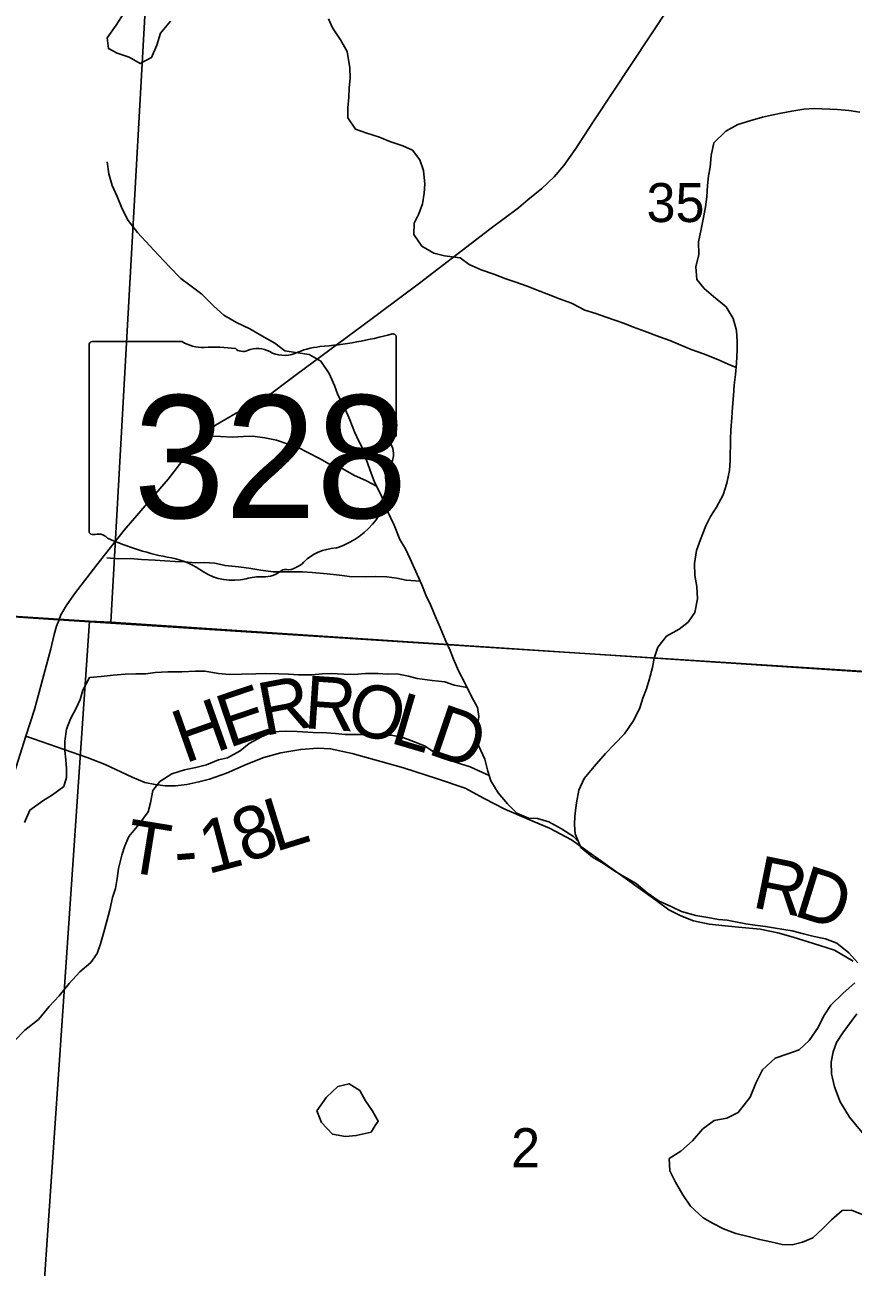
# Model space of a CAD drawing. Extents: x 0 to 34, y 0 to 22.
# Drawn here: x 3.309 to 4.198, y 18.42 to 19.753 of the extents above; entities that cross this region are included whole.
import ezdxf

# ---------------------------------------------------------------- set-up
doc = ezdxf.new("R2010")
doc.units = 0
for name, color, linetype in [('GM_X_Major_River', 7, 'Continuous'), ('GM_X_Minor_Lake', 7, 'Continuous'), ('GM_X_Minor_River', 7, 'Continuous'), ('GM_X_Section', 7, 'Continuous'), ('GM_X_Section_Text', 7, 'Continuous'), ('GM_X_State_Location', 7, 'Continuous'), ('GM_X_State_Route', 7, 'Continuous'), ('GM_X_State_Shield', 7, 'Continuous'), ('GM_X_Township_Road', 7, 'Continuous'), ('GM_X_Township_Road_Text', 7, 'Continuous'), ('SC_Scratch1', 7, 'Continuous')]:
    doc.layers.add(name, color=color, linetype=linetype)

msp = doc.modelspace()

# ---------------------------------------------------------------- linework, layer by layer
at = {"layer": 'GM_X_Major_River'}
for points in [[(3.9032, 18.9318), (3.909, 18.9443), (3.9197, 18.9571), (3.9319, 18.9711), (3.9415, 18.9812), (3.9525, 18.9922), (3.9625, 19.0069), (3.969, 19.0201), (3.9721, 19.0307), (3.976, 19.0405), (3.9787, 19.0504), (3.9826, 19.0636), (3.9842, 19.0735), (3.9881, 19.0852), (3.9976, 19.0973), (4.011, 19.1048), (4.0209, 19.1123), (4.0278, 19.1225), (4.0309, 19.1373), (4.0302, 19.1505), (4.028, 19.1623), (4.0274, 19.1752), (4.0297, 19.1892), (4.034, 19.201), (4.0398, 19.2157), (4.0448, 19.2255), (4.0513, 19.2357), (4.0582, 19.249), (4.0621, 19.2615), (4.0652, 19.2751), (4.066, 19.2853), (4.0662, 19.3088), (4.0666, 19.3183), (4.0675, 19.332), (4.0683, 19.343), (4.0695, 19.3555), (4.07, 19.3665), (4.0716, 19.3782), (4.0728, 19.3903), (4.0732, 19.404), (4.0733, 19.4135), (4.0726, 19.4252), (4.0689, 19.4382), (4.0614, 19.4507), (4.0478, 19.4618), (4.038, 19.4703), (4.0301, 19.4802), (4.0291, 19.4938), (4.0322, 19.5067), (4.0319, 19.5204), (4.0347, 19.534), (4.0374, 19.5484), (4.0394, 19.5579), (4.0406, 19.5689), (4.0414, 19.581), (4.0426, 19.5912), (4.0442, 19.6007), (4.0454, 19.6132), (4.0482, 19.6269), (4.0611, 19.6393), (4.0741, 19.6464), (4.087, 19.6505), (4.1007, 19.6542), (4.1102, 19.6564), (4.1205, 19.6586), (4.1322, 19.6608), (4.1451, 19.6629), (4.1561, 19.6636), (4.1812, 19.6627), (4.1933, 19.6614), (4.205, 19.6598)], [(4.2028, 18.7464), (4.1934, 18.7571), (4.1805, 18.7674), (4.1681, 18.7721), (4.1559, 18.7748), (4.1446, 18.7775), (4.1325, 18.7807), (4.1146, 18.7835), (4.1037, 18.7854), (4.0923, 18.787), (4.0828, 18.7882), (4.0734, 18.7902), (4.0627, 18.7922), (4.0533, 18.793), (4.0419, 18.795), (4.029, 18.7974), (4.0135, 18.8017), (4.0033, 18.8067), (3.9897, 18.8125), (3.9768, 18.8216), (3.9648, 18.8316), (3.9542, 18.8378), (3.9421, 18.8447), (3.93, 18.8531), (3.9179, 18.86), (3.9055, 18.8704), (3.8995, 18.8848), (3.8988, 18.8947), (3.8992, 18.9042), (3.9009, 18.9182), (3.9032, 18.9318)], [(4.2093, 18.4755), (4.1961, 18.4809), (4.1862, 18.4806), (4.1748, 18.4704), (4.1649, 18.461), (4.1546, 18.4512), (4.1435, 18.4464), (4.1325, 18.4438), (4.1215, 18.4442), (4.1094, 18.447), (4.0976, 18.4494), (4.0852, 18.4525), (4.0719, 18.456), (4.0587, 18.461), (4.0469, 18.4668), (4.0367, 18.4726), (4.0232, 18.4852), (4.0149, 18.4974), (4.007, 18.5111), (4.001, 18.5233), (4.0004, 18.5362), (4.0129, 18.5441), (4.0255, 18.5554), (4.0366, 18.5682), (4.0488, 18.5772), (4.0621, 18.5797), (4.0743, 18.5857), (4.0873, 18.6023), (4.0934, 18.6174), (4.1007, 18.6314), (4.1141, 18.6439), (4.1278, 18.6487), (4.14, 18.6531), (4.1506, 18.6629), (4.1602, 18.6769), (4.1664, 18.6894), (4.174, 18.7011), (4.187, 18.7139), (4.1996, 18.7248)]]:
    msp.add_lwpolyline(points, dxfattribs=at)
at = {"layer": 'GM_X_Minor_Lake'}
for points in [[(3.6848, 18.5718), (3.6879, 18.5765), (3.6814, 18.5879), (3.6742, 18.5981), (3.6681, 18.6095), (3.6567, 18.6166), (3.6446, 18.6136), (3.6325, 18.6022), (3.622, 18.5874)], [(3.622, 18.5874), (3.6269, 18.5749), (3.6387, 18.5624), (3.6527, 18.5601), (3.6644, 18.5609), (3.6803, 18.5647), (3.6848, 18.5718)]]:
    msp.add_lwpolyline(points, dxfattribs=at)
at = {"layer": 'GM_X_Minor_River'}
for points in [[(3.4649, 19.7573), (3.4543, 19.7444), (3.4502, 19.7315), (3.4446, 19.7182), (3.4325, 19.7118), (3.4207, 19.7186), (3.4078, 19.7231), (3.3983, 19.728), (3.3968, 19.7393), (3.4066, 19.753), (3.4149, 19.7659)], [(4.0723, 19.3857), (4.0638, 19.3892), (4.0509, 19.3948), (4.0372, 19.4001), (4.024, 19.405), (4.0103, 19.4106), (4.0009, 19.4144), (3.9899, 19.4186), (3.9739, 19.4246), (3.9622, 19.4287), (3.9523, 19.4329), (3.9421, 19.4363), (3.9326, 19.4396), (3.9216, 19.4434), (3.9099, 19.4472), (3.8955, 19.4547), (3.8826, 19.4592), (3.8709, 19.4641), (3.8614, 19.4675), (3.8477, 19.4728), (3.8345, 19.4777), (3.825, 19.4807), (3.8121, 19.4856), (3.7985, 19.4905), (3.7856, 19.4962), (3.7761, 19.5033), (3.7591, 19.5056), (3.7477, 19.5082), (3.7348, 19.5157), (3.726, 19.5282), (3.7264, 19.5404), (3.7317, 19.5506), (3.7354, 19.5612), (3.7373, 19.5726), (3.738, 19.5825), (3.7364, 19.5969), (3.7326, 19.6086), (3.7246, 19.6188), (3.7144, 19.6234), (3.7004, 19.6283), (3.6894, 19.6328), (3.6757, 19.6373), (3.6636, 19.6414), (3.6552, 19.6535), (3.6552, 19.6642), (3.6563, 19.6759), (3.6566, 19.6858), (3.6577, 19.696), (3.6573, 19.7074), (3.6546, 19.7248), (3.6474, 19.7373), (3.639, 19.7502), (3.6345, 19.76)], [(3.903, 18.8764), (3.8977, 18.8819), (3.8848, 18.8902), (3.8712, 18.8977), (3.859, 18.9015), (3.8492, 18.9018), (3.8367, 18.9071), (3.8268, 18.917), (3.8169, 18.9291), (3.8089, 18.9419), (3.8055, 18.9522), (3.8024, 18.965), (3.796, 18.9791), (3.7933, 18.9919), (3.7944, 19.0014), (3.7959, 19.0109), (3.7947, 19.0204), (3.7882, 19.0325), (3.781, 19.0469), (3.7741, 19.0598), (3.7688, 19.0723), (3.7653, 19.0817), (3.7604, 19.0916), (3.7543, 19.1063), (3.7493, 19.1177), (3.7444, 19.1302), (3.7394, 19.1404), (3.7348, 19.1522), (3.7283, 19.1666), (3.7222, 19.1802), (3.7173, 19.1908), (3.7112, 19.201), (3.7051, 19.2162), (3.6975, 19.2321), (3.691, 19.2484), (3.6838, 19.2624), (3.6803, 19.2722), (3.6753, 19.2859), (3.6727, 19.2953), (3.667, 19.3063), (3.6624, 19.3165), (3.6574, 19.3294), (3.6517, 19.3427), (3.6445, 19.3563), (3.641, 19.3661), (3.6353, 19.379), (3.6262, 19.3923), (3.6137, 19.3994), (3.6015, 19.4013), (3.5875, 19.4035), (3.5769, 19.4115), (3.5629, 19.4194), (3.55, 19.427), (3.5359, 19.4337), (3.5223, 19.4417), (3.5113, 19.4515), (3.4984, 19.4644), (3.4855, 19.4738), (3.476, 19.481), (3.4642, 19.4931), (3.4521, 19.5063), (3.4426, 19.5162), (3.4296, 19.5305), (3.4194, 19.5434), (3.4129, 19.5559), (3.4076, 19.5692), (3.4022, 19.5809), (3.3988, 19.5934), (3.3968, 19.6063)], [(3.686, 19.258), (3.6754, 19.2639), (3.6618, 19.2699), (3.65, 19.2767), (3.6383, 19.2805), (3.625, 19.288), (3.6125, 19.2944), (3.6011, 19.3001), (3.5913, 19.3031), (3.5787, 19.3076), (3.5662, 19.3099), (3.5534, 19.3117), (3.5432, 19.3113), (3.531, 19.3109), (3.5185, 19.3116), (3.5068, 19.312)], [(3.733, 19.1563), (3.7178, 19.1571), (3.7079, 19.1593), (3.6973, 19.1608), (3.6848, 19.1611), (3.6742, 19.1607), (3.6572, 19.1611), (3.6462, 19.1626), (3.633, 19.1641), (3.6171, 19.1655), (3.6068, 19.1663), (3.575, 19.1662), (3.5618, 19.168), (3.5489, 19.1703), (3.5379, 19.1714), (3.5235, 19.1729), (3.5125, 19.1755), (3.5012, 19.1762), (3.4913, 19.1758), (3.4804, 19.1769), (3.4698, 19.1773), (3.4588, 19.178), (3.4486, 19.1788), (3.4338, 19.1795), (3.4217, 19.1806), (3.4088, 19.1802), (3.3967, 19.1813)], [(3.7834, 19.042), (3.7696, 19.0446), (3.7594, 19.048), (3.7458, 19.0495), (3.7299, 19.0517), (3.7204, 19.0543), (3.7079, 19.0566), (3.698, 19.0562), (3.6878, 19.0569), (3.6742, 19.0569), (3.6617, 19.0561), (3.6511, 19.0564), (3.6375, 19.0572), (3.6276, 19.0567), (3.6167, 19.0556), (3.6023, 19.0555), (3.5917, 19.0563), (3.5811, 19.0566), (3.5671, 19.057), (3.5565, 19.0566), (3.5413, 19.0562), (3.5281, 19.0561), (3.5163, 19.0572), (3.5019, 19.0595), (3.4917, 19.0594), (3.477, 19.0587), (3.4622, 19.059), (3.4486, 19.0582), (3.4384, 19.0567), (3.4278, 19.0566), (3.4164, 19.0562), (3.4035, 19.0554), (3.3903, 19.0539), (3.3778, 19.0527), (3.3707, 19.0391), (3.368, 19.0292), (3.3635, 19.0197), (3.3575, 19.0083), (3.3534, 18.9973), (3.3515, 18.9844), (3.3516, 18.9742), (3.3524, 18.9643), (3.3531, 18.9549), (3.3532, 18.9454), (3.3502, 18.9359), (3.3381, 18.9268), (3.3279, 18.9203), (3.3139, 18.9104), (3.3083, 18.8971)], [(3.8071, 18.9474), (3.796, 18.9525), (3.7866, 18.9567), (3.7763, 18.9601), (3.7665, 18.9634), (3.7517, 18.9702), (3.7384, 18.9789), (3.7286, 18.9831), (3.7142, 18.9883), (3.702, 18.991), (3.6914, 18.9909), (3.6793, 18.9917), (3.6524, 18.9916), (3.6422, 18.9927), (3.6324, 18.9934), (3.618, 18.9938), (3.601, 18.9949), (3.5881, 18.9952), (3.5748, 18.9944), (3.5627, 18.9891), (3.5495, 18.9819), (3.5397, 18.9739), (3.5261, 18.9666), (3.5163, 18.9643), (3.5034, 18.959), (3.4921, 18.9563), (3.48, 18.9536), (3.4663, 18.9494), (3.4535, 18.9411), (3.446, 18.9316), (3.4433, 18.9183), (3.4411, 18.9084), (3.4309, 18.8951), (3.42, 18.8822), (3.4159, 18.872), (3.4125, 18.8621), (3.4091, 18.8477), (3.4076, 18.8371), (3.4058, 18.8264), (3.4028, 18.8166), (3.3998, 18.8033), (3.3968, 18.7927), (3.3934, 18.7794), (3.3897, 18.7669), (3.386, 18.7563), (3.3792, 18.7468), (3.3675, 18.7369), (3.3562, 18.7243), (3.3452, 18.711), (3.3347, 18.6996), (3.323, 18.6856), (3.3086, 18.6742), (3.2973, 18.6628)]]:
    msp.add_lwpolyline(points, dxfattribs=at)
at = {"layer": 'GM_X_Section'}
for points in [[(3.4572, 20.1141), (3.4007, 19.112), (3.378, 19.1131), (2.3838, 19.1776), (2.446, 20.1823)], [(4.4687, 20.0485), (4.4009, 19.0464), (4.3808, 19.0475), (3.4007, 19.112), (3.4572, 20.1141)], [(2.3543, 19.1806), (2.3838, 19.1776), (3.378, 19.1131), (3.3075, 18.0826), (2.2906, 18.1558)], [(3.378, 19.1131), (3.4007, 19.112), (4.3808, 19.0475), (4.3187, 18.0057), (3.3075, 18.0826)]]:
    msp.add_lwpolyline(points, close=True, dxfattribs=at)
at = {"layer": 'GM_X_State_Route'}
for points in [[(3.8486, 19.5654), (3.8636, 19.5777), (3.8768, 19.5901), (3.8872, 19.6025), (3.8994, 19.6195), (3.9187, 19.6494), (4.0213, 19.8045)], [(3.6886, 19.4434), (3.7324, 19.476), (3.8076, 19.5342), (3.8384, 19.557), (3.8486, 19.5654)], [(3.3095, 18.9897), (3.3188, 19.0184), (3.3365, 19.0837), (3.3399, 19.0989), (3.3424, 19.1077), (3.345, 19.1141), (3.3473, 19.1199), (3.353, 19.1297), (3.3618, 19.1426), (3.3859, 19.1737), (3.4153, 19.211), (3.4623, 19.2657), (3.4869, 19.2972), (3.4966, 19.3092), (3.5131, 19.3237), (3.5354, 19.3366), (3.5641, 19.351), (3.6003, 19.378), (3.6813, 19.438), (3.6886, 19.4434)], [(3.2872, 18.9182), (3.3095, 18.9897)]]:
    msp.add_lwpolyline(points, dxfattribs=at)
at = {"layer": 'GM_X_State_Shield'}
for p, q in [((3.3776, 19.4099), (3.3776, 19.2097)), ((3.4774, 19.4133), (3.3809, 19.4133)), ((3.7072, 19.3136), (3.7072, 19.4183)), ((3.7072, 19.3136), (3.7072, 19.3136))]:
    msp.add_line(p, q, dxfattribs=at)
for centre, major_axis, start_param, end_param in [((3.5898, 19.6861), (0.3495, 0), 4.814394, 5.042369), ((3.7036, 19.4187), (0.00367, 0), 6.141152, 7.989035), ((3.3814, 19.4103), (0.00382, 0), 1.712693, 3.28349), ((3.5004, 19.4365), (0.037, 0), 4.042523, 4.731795), ((3.5127, 19.301), (0.133, 0), 1.404758, 1.657858), ((3.5428, 19.4113), (0.0107, 0), 3.836095, 5.185415), ((3.5585, 19.3882), (0.0222, 0), 0.950623, 2.079405), ((3.6344, 19.3522), (0.0703, 0), 1.699011, 2.107814), ((3.5872, 19.4199), (0.0267, 0), 4.081561, 5.145723), ((3.7033, 19.3132), (0.00393, 0), 5.05454, 6.418171), ((3.7064, 19.3059), (0.00568, 0), 1.883978, 3.671073), ((3.6702, 19.2927), (0.0341, 0), 5.934695, 6.695948), ((3.7204, 19.2698), (0.0248, 0), 2.387724, 3.262537), ((3.6094, 19.2564), (0.0874, 0), 5.101752, 6.440018), ((3.3814, 19.2093), (0.00385, 0), 3.00124, 4.508301), ((3.382, 19.2298), (0.0294, 0), 4.665946, 4.897461), ((3.388, 19.1982), (0.0106, 0), 0.519207, 1.627899), ((3.5219, 19.378), (0.2524, 0), 4.195997, 4.488961), ((3.4466, 19.1198), (0.079, 0), 0.823519, 1.323587), ((3.6463, 19.1536), (0.0479, 0), 1.647645, 2.488434), ((3.532, 19.1972), (0.0501, 0), 4.026481, 4.996735), ((3.5646, 19.1822), (0.0267, 0), 4.691044, 5.507374), ((3.5888, 19.1628), (0.00752, 0), 1.147584, 2.315152), ((3.5856, 19.1903), (0.0282, 0), 4.937069, 5.64225), ((3.561, 19.128), (0.0412, 0), 1.495662, 1.94098)]:
    msp.add_ellipse(centre, major_axis=major_axis, ratio=0.8, start_param=start_param, end_param=end_param, dxfattribs=at)
at = {"layer": 'GM_X_Township_Road'}
for points in [[(3.3095, 18.9897), (3.3756, 18.9667), (3.3949, 18.9593), (3.4237, 18.9459), (3.4372, 18.9402), (3.4485, 18.9377), (3.4593, 18.9365), (3.4703, 18.9365), (3.4823, 18.9377), (3.4955, 18.9406), (3.5067, 18.9436), (3.5249, 18.9499), (3.5463, 18.9593), (3.5651, 18.9669), (3.5833, 18.9719), (3.6047, 18.9756), (3.6231, 18.9768), (3.6367, 18.9763), (3.6599, 18.971), (3.7151, 18.9556), (3.7517, 18.9439), (3.7814, 18.9338), (3.8016, 18.9227), (3.8239, 18.9114), (3.8495, 18.9004), (3.872, 18.891), (3.8955, 18.8785), (3.9341, 18.8509), (3.9859, 18.8137), (4.0001, 18.8035), (4.013, 18.7969), (4.0266, 18.7914), (4.0434, 18.7881), (4.0604, 18.7861), (4.0747, 18.7847), (4.0981, 18.7824), (4.117, 18.7787), (4.1336, 18.7741), (4.1554, 18.7672), (4.178, 18.7601), (4.198, 18.7481)], [(4.2017, 18.6915), (4.1869, 18.6713), (4.18, 18.6609), (4.1763, 18.6508), (4.1743, 18.6398), (4.1747, 18.6273), (4.178, 18.6133), (4.1839, 18.5972), (4.1938, 18.5809), (4.2143, 18.556)]]:
    msp.add_lwpolyline(points, dxfattribs=at)
at = {"layer": 'SC_Scratch1'}
for points in [[(5.53, 20.9), (2.1, 20.9), (2.1, 19.1982), (2.3572, 19.1804), (3.3448, 19.1146), (4.3628, 19.0495), (4.7394, 19.0241), (4.7997, 19.0196), (5.182, 18.9932), (5.4007, 18.9779), (5.4089, 19.0989), (5.4469, 19.6641), (5.4955, 20.3864)], [(2.1, 19.1982), (2.1, 14.1), (5.0535, 14.1), (5.0814, 14.5016), (5.1049, 14.8414), (5.1794, 15.9156), (5.2761, 17.2534), (5.2869, 17.4026), (5.3506, 18.2846), (5.3662, 18.4999), (5.4007, 18.9779), (5.182, 18.9932), (4.7997, 19.0196), (4.7394, 19.0241), (4.3628, 19.0495), (3.3448, 19.1146), (2.3572, 19.1804)]]:
    msp.add_lwpolyline(points, close=True, dxfattribs=at)

# ---------------------------------------------------------------- texts
at = {"layer": 'GM_X_Section_Text'}
for s, height, p in [('35', 0.04186, (3.976, 19.5417)), ('2', 0.0419, (3.8306, 18.527))]:
    msp.add_text(s, height=height, rotation=0, dxfattribs=at).set_placement(p)
at = {"layer": 'GM_X_State_Location'}
for s in ['s', 'r']:
    msp.add_text(s, height=0.000189, dxfattribs=at).set_placement((3.5387, 19.2965))
msp.add_text('328', height=0.000189, rotation=0, dxfattribs=at).set_placement((3.4719, 19.2827))
at = {"layer": 'GM_X_State_Shield'}
msp.add_text('328', height=0.13184, dxfattribs=at).set_placement((3.4252, 19.2239))
at = {"layer": 'GM_X_Township_Road_Text'}
for s, rotation, p in [('E', 18.6531, (3.5271, 18.9768)), ('R', 10.7772, (3.5654, 18.9899)), ('R', 356.1919, (3.6074, 18.9984)), ('O', 345.2861, (3.6512, 18.9957)), ('L', 343.5943, (3.6991, 18.9831)), ('H', 19.5178, (3.4802, 18.9602)), ('D', 341.2033, (3.7393, 18.9713)), ('8', 21.7303, (3.5457, 18.8526)), ('L', 17.283, (3.5771, 18.8652)), ('T', 350.8068, (3.4138, 18.845)), ('1', 14.706, (3.5046, 18.8414)), ('-', 4.704, (3.4707, 18.8377)), ('R', 348.6265, (4.088, 18.8064)), ('D', 342.6629, (4.1322, 18.7976))]:
    msp.add_text(s, height=0.0568, rotation=rotation, dxfattribs=at).set_placement(p)

doc.saveas('drawing.dxf')
